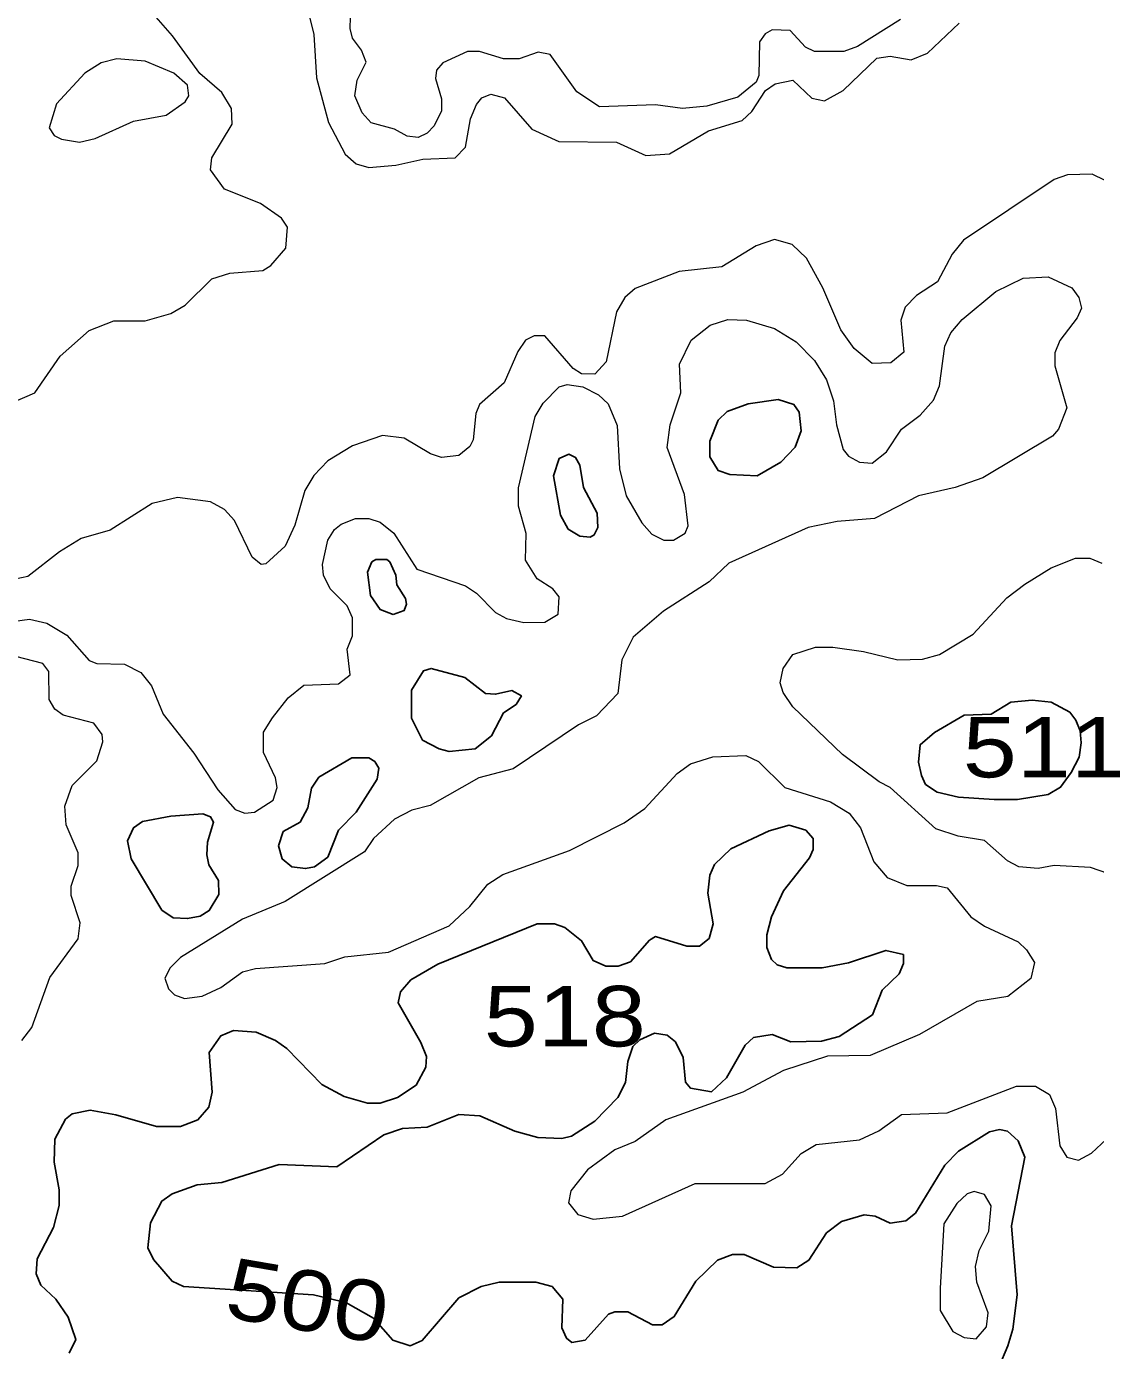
# Model space of a CAD drawing. Extents: x 577 to 602.9, y 7483.8 to 7511.6.
# Drawn here: x 591.332 to 592.745, y 7498.971 to 7500.722 of the extents above; entities that cross this region are included whole.
import ezdxf
from ezdxf.enums import TextEntityAlignment as Align

# ---------------------------------------------------------------- set-up
doc = ezdxf.new("R2010")
doc.units = 0
doc.header["$LTSCALE"] = 0.032
doc.layers.add('1', color=7, linetype='Continuous', lineweight=25)
doc.layers.add('2', color=7, linetype='Continuous', lineweight=13)
doc.layers.add('61', color=7, linetype='Continuous')

msp = doc.modelspace()

# ---------------------------------------------------------------- linework, layer by layer
at = {"layer": '1'}
for points in [[(592.2618, 7500.1298), (592.2979, 7500.1278), (592.3289, 7500.1461), (592.3479, 7500.166), (592.3559, 7500.1874), (592.3535, 7500.2121), (592.3464, 7500.2224), (592.3257, 7500.2288), (592.2859, 7500.2232), (592.2581, 7500.2129), (592.2462, 7500.2017), (592.235, 7500.1739), (592.235, 7500.1532), (592.2462, 7500.135)], [(592.0479, 7500.0574), (592.0633, 7500.0483), (592.0768, 7500.0467), (592.0824, 7500.0499), (592.0871, 7500.0594), (592.0863, 7500.0785), (592.068, 7500.1127), (592.0633, 7500.1421), (592.0577, 7500.1524), (592.049, 7500.1564), (592.0362, 7500.1509), (592.0283, 7500.1278), (592.0378, 7500.0761)], [(591.8167, 7499.9447), (591.8311, 7499.9497), (591.8343, 7499.9584), (591.8327, 7499.9656), (591.8215, 7499.9839), (591.82, 7499.9966), (591.812, 7500.0141), (591.808, 7500.0173), (591.7937, 7500.0173), (591.7881, 7500.0141), (591.7826, 7500.0006), (591.7866, 7499.9696), (591.7993, 7499.9513)], [(591.8553, 7499.7784), (591.8772, 7499.7668), (591.8907, 7499.7636), (591.9249, 7499.7668), (591.9464, 7499.7843), (591.9623, 7499.8145), (591.979, 7499.8256), (591.9861, 7499.8368), (591.9734, 7499.8439), (591.952, 7499.8391), (591.9384, 7499.8399), (591.9114, 7499.8614), (591.8669, 7499.8733), (591.8565, 7499.8702), (591.8406, 7499.8447), (591.8406, 7499.8073)], [(592.6824, 7499.7065), (592.699, 7499.7161), (592.7129, 7499.7358), (592.7234, 7499.7559), (592.726, 7499.7747), (592.7247, 7499.7908), (592.7193, 7499.805), (592.7113, 7499.8153), (592.6867, 7499.8288), (592.6612, 7499.8312), (592.6334, 7499.8288), (592.6072, 7499.8129), (592.5714, 7499.8113), (592.5324, 7499.7883), (592.5133, 7499.7724), (592.511, 7499.7493), (592.5149, 7499.7318), (592.5205, 7499.7199), (592.5356, 7499.7095), (592.5642, 7499.7032), (592.6112, 7499.7), (592.6422, 7499.7)], [(591.6711, 7499.6574), (591.6935, 7499.6698), (591.7039, 7499.6889), (591.7086, 7499.7151), (591.7182, 7499.7294), (591.7619, 7499.7549), (591.7842, 7499.7549), (591.7921, 7499.7501), (591.7977, 7499.7413), (591.7953, 7499.727), (591.7675, 7499.6833), (591.7444, 7499.6594), (591.7301, 7499.6237), (591.7126, 7499.6109), (591.7007, 7499.6085), (591.6824, 7499.6109), (591.6697, 7499.6213), (591.6649, 7499.6388)], [(591.5702, 7499.6268), (591.5711, 7499.6435), (591.579, 7499.6698), (591.575, 7499.6769), (591.5647, 7499.6809), (591.5226, 7499.6777), (591.4852, 7499.6706), (591.4733, 7499.6626), (591.4653, 7499.6451), (591.4701, 7499.6213), (591.5106, 7499.5537), (591.5257, 7499.5433), (591.5448, 7499.5425), (591.5615, 7499.5457), (591.5734, 7499.5529), (591.5862, 7499.5744), (591.5854, 7499.5926), (591.5727, 7499.6133)]]:
    msp.add_lwpolyline(points, close=True, dxfattribs=at)
for points in [[(591.3882, 7498.9676), (591.3969, 7498.9859), (591.3866, 7499.0153), (591.3707, 7499.0392), (591.3508, 7499.0575), (591.3444, 7499.0726), (591.346, 7499.0925), (591.3675, 7499.1338), (591.3747, 7499.1632), (591.3747, 7499.1839), (591.3683, 7499.2205), (591.3691, 7499.2507), (591.3834, 7499.277), (591.3921, 7499.2841), (591.416, 7499.2889), (591.4499, 7499.2827), (591.5035, 7499.2674), (591.5353, 7499.2674), (591.5583, 7499.2762), (591.5727, 7499.2929), (591.5774, 7499.3127), (591.5734, 7499.3652), (591.5886, 7499.3875), (591.6053, 7499.3946), (591.6355, 7499.3923), (591.6609, 7499.3811), (591.676, 7499.3708), (591.7221, 7499.3231), (591.7516, 7499.3072), (591.7826, 7499.2984), (591.7993, 7499.2984), (591.8223, 7499.3056), (591.847, 7499.3223), (591.8598, 7499.346), (591.8607, 7499.36), (591.8532, 7499.3787), (591.8231, 7499.4312), (591.8263, 7499.4455), (591.8398, 7499.4614), (591.8756, 7499.4821), (592.0068, 7499.5354), (592.0299, 7499.5354), (592.0434, 7499.5306), (592.0657, 7499.5131), (592.0808, 7499.4869), (592.0975, 7499.4797), (592.1142, 7499.4797), (592.1301, 7499.4853), (592.1555, 7499.5139), (592.1635, 7499.5187), (592.2048, 7499.506), (592.2215, 7499.506), (592.2342, 7499.5163), (592.2398, 7499.5354), (592.2326, 7499.5759), (592.235, 7499.5998), (592.2414, 7499.6141), (592.2629, 7499.6348), (592.3138, 7499.6586), (592.34, 7499.6658), (592.3623, 7499.6594)], [(592.3623, 7499.6594), (592.3718, 7499.6483), (592.3718, 7499.634), (592.367, 7499.6229), (592.3328, 7499.5791), (592.3169, 7499.5449), (592.3106, 7499.5211), (592.3106, 7499.5044), (592.3169, 7499.4885), (592.3241, 7499.4813), (592.3368, 7499.4773), (592.3837, 7499.4773), (592.4187, 7499.4837), (592.468, 7499.5004), (592.4911, 7499.4948), (592.4911, 7499.4829), (592.4855, 7499.4694), (592.4632, 7499.4479), (592.4505, 7499.4153), (592.406, 7499.3867), (592.3829, 7499.3803), (592.3424, 7499.3795), (592.3177, 7499.3891), (592.2931, 7499.3851), (592.2819, 7499.3748), (592.2573, 7499.3318), (592.2374, 7499.3135), (592.2096, 7499.3183), (592.2032, 7499.3263), (592.2, 7499.3589), (592.1897, 7499.3795), (592.1786, 7499.3883), (592.1619, 7499.3907), (592.1428, 7499.3819), (592.1333, 7499.3732), (592.1269, 7499.3533), (592.1237, 7499.3255), (592.1134, 7499.3056), (592.0832, 7499.2746), (592.0521, 7499.2547), (592.0394, 7499.2515), (592.0076, 7499.2531), (591.9774, 7499.2611), (591.9313, 7499.2817), (591.9034, 7499.2833), (591.8613, 7499.2666), (591.8287, 7499.265), (591.804, 7499.2563), (591.742, 7499.2141), (591.6657, 7499.2173), (591.5901, 7499.1935), (591.5575, 7499.1903), (591.5241, 7499.1784), (591.5106, 7499.1688), (591.4955, 7499.1402), (591.4923, 7499.1068), (591.4995, 7499.0917), (591.5241, 7499.0631), (591.5393, 7499.0559), (591.7112, 7499.0448), (591.7541, 7499.0345), (591.7905, 7499.0138), (591.816, 7498.9851), (591.839, 7498.9772), (591.8549, 7498.9843), (591.9034, 7499.0408), (591.9329, 7499.0559), (591.9567, 7499.0615), (592.0052, 7499.0615), (592.0267, 7499.0559), (592.041, 7499.0392), (592.0394, 7499.001), (592.0458, 7498.9875), (592.0529, 7498.9819), (592.0704, 7498.9851), (592.1014, 7499.0193), (592.1094, 7499.0225), (592.1269, 7499.0225), (592.1595, 7499.005), (592.1722, 7499.005), (592.1881, 7499.0161), (592.2167, 7499.0631), (592.2454, 7499.0909), (592.2652, 7499.098), (592.2804, 7499.098), (592.3193, 7499.0813), (592.3503, 7499.0805), (592.3662, 7499.0909), (592.3893, 7499.1267), (592.4092, 7499.1418), (592.4394, 7499.1505), (592.4537, 7499.1489), (592.4736, 7499.1394), (592.4943, 7499.1426), (592.507, 7499.1529), (592.5459, 7499.2165), (592.5642, 7499.2348), (592.6048, 7499.2603), (592.6183, 7499.2634), (592.6286, 7499.2611), (592.643, 7499.2483)], [(592.643, 7499.2483), (592.6517, 7499.2269), (592.6342, 7499.1362), (592.6414, 7499.0448), (592.6358, 7498.9994), (592.6294, 7498.9772), (592.6175, 7498.9493)]]:
    msp.add_lwpolyline(points, dxfattribs=at)
at = {"layer": '2'}
for points in [[(591.6029, 7500.6136), (591.5901, 7500.6351), (591.5607, 7500.6598), (591.5249, 7500.7099), (591.4971, 7500.7417)], [(591.7054, 7500.7369), (591.7118, 7500.7115), (591.715, 7500.6542), (591.7309, 7500.5954), (591.7532, 7500.5532), (591.7675, 7500.5405), (591.7842, 7500.5357), (591.82, 7500.5389), (591.8557, 7500.5469), (591.8987, 7500.5484), (591.9122, 7500.5628), (591.9186, 7500.6001), (591.9265, 7500.6192), (591.9337, 7500.628), (591.9456, 7500.6327), (591.9639, 7500.628), (591.9997, 7500.5866), (592.0354, 7500.5699), (592.1118, 7500.5691), (592.1507, 7500.5516), (592.1818, 7500.554), (592.2334, 7500.5842), (592.278, 7500.5977), (592.2907, 7500.6097), (592.309, 7500.6375), (592.3217, 7500.6463), (592.3448, 7500.651), (592.3702, 7500.6272), (592.3869, 7500.624), (592.4116, 7500.6375), (592.4561, 7500.6804), (592.4736, 7500.6828), (592.5014, 7500.6781), (592.5229, 7500.6868), (592.565, 7500.7266)], [(592.4871, 7500.7313), (592.4306, 7500.6956), (592.4124, 7500.6892), (592.3734, 7500.6892), (592.3615, 7500.6948), (592.3416, 7500.717), (592.3177, 7500.7178), (592.3082, 7500.7123), (592.301, 7500.7019), (592.3002, 7500.6574), (592.2963, 7500.6486), (592.2724, 7500.6288), (592.2311, 7500.6168), (592.1992, 7500.6136), (592.1635, 7500.6184), (592.0895, 7500.616), (592.0593, 7500.6359), (592.0243, 7500.6852), (592.0084, 7500.6884), (591.983, 7500.6796), (591.9623, 7500.6796), (591.9305, 7500.6892), (591.9146, 7500.6892), (591.882, 7500.6741), (591.874, 7500.6645), (591.8724, 7500.6534), (591.8804, 7500.6264), (591.8804, 7500.6105), (591.8708, 7500.5906), (591.8613, 7500.581), (591.8494, 7500.5755), (591.8351, 7500.5771), (591.8184, 7500.5866), (591.7873, 7500.5946), (591.7754, 7500.6081), (591.7659, 7500.6303), (591.7691, 7500.651), (591.781, 7500.6749), (591.7746, 7500.6908), (591.7627, 7500.7067), (591.7595, 7500.7194), (591.7603, 7500.7345)], [(591.3134, 7500.2248), (591.3428, 7500.2375), (591.3762, 7500.286), (591.4144, 7500.3202), (591.447, 7500.333), (591.4884, 7500.333), (591.5226, 7500.3425), (591.5416, 7500.3536), (591.5766, 7500.3886), (591.6005, 7500.3958), (591.6442, 7500.3997), (591.6546, 7500.4061), (591.6744, 7500.4292), (591.6768, 7500.457), (591.6689, 7500.4689), (591.641, 7500.488), (591.5933, 7500.5071), (591.575, 7500.5325), (591.5766, 7500.5484), (591.6037, 7500.593), (591.6029, 7500.6136)], [(592.775, 7500.5103), (592.7408, 7500.527), (592.7082, 7500.5262), (592.6907, 7500.5198), (592.5706, 7500.4395), (592.5555, 7500.4212), (592.5364, 7500.3846), (592.5086, 7500.3663), (592.4935, 7500.3512), (592.4879, 7500.3337), (592.4919, 7500.2916), (592.4744, 7500.2773), (592.4497, 7500.2765), (592.4259, 7500.2964), (592.4084, 7500.321), (592.3845, 7500.3767), (592.3631, 7500.4157), (592.344, 7500.4339), (592.3209, 7500.4403), (592.2963, 7500.4323), (592.2509, 7500.4045), (592.1945, 7500.3982), (592.1364, 7500.3759), (592.1229, 7500.364), (592.1118, 7500.3449), (592.0983, 7500.2789), (592.0832, 7500.2622), (592.0657, 7500.263), (592.0545, 7500.2701), (592.0172, 7500.3131), (592.0028, 7500.3131), (591.9917, 7500.3075), (591.9814, 7500.2924), (591.9631, 7500.251), (591.9305, 7500.2224), (591.9257, 7500.2105), (591.9225, 7500.1755), (591.9178, 7500.1668), (591.9034, 7500.1548), (591.8804, 7500.1524), (591.8661, 7500.1572), (591.8311, 7500.1779), (591.8025, 7500.1811), (591.7627, 7500.1676), (591.7301, 7500.1477), (591.7118, 7500.1286), (591.6999, 7500.1087), (591.6864, 7500.0626), (591.6736, 7500.0348), (591.6482, 7500.0117), (591.6418, 7500.0109), (591.6299, 7500.0204), (591.6068, 7500.069), (591.5933, 7500.0833), (591.575, 7500.0936), (591.5313, 7500.0992), (591.4979, 7500.0912), (591.4422, 7500.0562), (591.4041, 7500.0451), (591.3754, 7500.0276), (591.3333, 7499.995), (591.2745, 7499.9823)], [(591.5846, 7499.7127), (591.6076, 7499.6865), (591.6204, 7499.6817), (591.6331, 7499.6833), (591.6577, 7499.6992), (591.6633, 7499.7159), (591.6609, 7499.7286), (591.645, 7499.762), (591.645, 7499.7891), (591.6569, 7499.8081), (591.6776, 7499.8344), (591.6983, 7499.8511), (591.7444, 7499.8527), (591.7595, 7499.8646), (591.7555, 7499.8988), (591.7627, 7499.9163), (591.7627, 7499.9401), (591.7555, 7499.956), (591.7333, 7499.9783), (591.7245, 7499.9966), (591.7229, 7500.0109), (591.7301, 7500.0427), (591.7388, 7500.057), (591.7476, 7500.0642), (591.7667, 7500.0713), (591.7842, 7500.0713), (591.7993, 7500.0666), (591.8176, 7500.0523), (591.8478, 7500.0045), (591.9122, 7499.9823), (591.9265, 7499.9727), (591.952, 7499.9473), (591.9663, 7499.9393), (591.9893, 7499.9338), (592.0172, 7499.9346), (592.0346, 7499.9449), (592.0362, 7499.968), (592.0275, 7499.9783), (592.0068, 7499.9918), (591.9917, 7500.0165), (591.9925, 7500.0515), (591.9822, 7500.088), (591.9822, 7500.1119), (592.0044, 7500.2065), (592.0148, 7500.224), (592.0362, 7500.2455), (592.0466, 7500.2487), (592.0673, 7500.2455), (592.0879, 7500.2351), (592.1006, 7500.2232), (592.1126, 7500.1946), (592.1158, 7500.1373), (592.1245, 7500.1016), (592.1452, 7500.0658), (592.1587, 7500.0507), (592.1746, 7500.0427), (592.1873, 7500.0427), (592.2024, 7500.0523), (592.2064, 7500.0618), (592.2016, 7500.1031), (592.1786, 7500.1652), (592.1826, 7500.1954), (592.1969, 7500.2375), (592.1953, 7500.2757), (592.2104, 7500.3075), (592.2358, 7500.3274), (592.2589, 7500.3345), (592.2835, 7500.3337), (592.3209, 7500.3226), (592.3495, 7500.3051), (592.3734, 7500.2805), (592.3893, 7500.255), (592.3988, 7500.2272), (592.4028, 7500.1954), (592.4116, 7500.1628), (592.4187, 7500.154), (592.433, 7500.1461), (592.4497, 7500.1445), (592.4688, 7500.1596), (592.4887, 7500.1898), (592.5133, 7500.2081), (592.5308, 7500.228), (592.5388, 7500.2471), (592.5459, 7500.2996), (592.5539, 7500.317), (592.569, 7500.3345), (592.6135, 7500.3719), (592.6493, 7500.3894), (592.6827, 7500.391), (592.7137, 7500.3767), (592.7233, 7500.364), (592.7265, 7500.3497), (592.7209, 7500.3369), (592.6978, 7500.3067), (592.6915, 7500.2908), (592.6915, 7500.2733), (592.7074, 7500.2177), (592.6962, 7500.1898), (592.6883, 7500.1803), (592.596, 7500.1254), (592.5595, 7500.1127)], [(592.5595, 7500.1127), (592.511, 7500.1016), (592.4529, 7500.0713), (592.4036, 7500.0674), (592.3654, 7500.0594), (592.2605, 7500.0125), (592.2342, 7499.9878), (592.1738, 7499.9489), (592.134, 7499.9147), (592.1189, 7499.8845), (592.1134, 7499.8399), (592.0855, 7499.8105), (592.0617, 7499.7986), (591.975, 7499.7405), (591.9297, 7499.7286), (591.8653, 7499.692), (591.8414, 7499.6857), (591.8184, 7499.6738), (591.7905, 7499.6483), (591.7786, 7499.6308), (591.6737, 7499.565), (591.6172, 7499.5418), (591.5353, 7499.4909), (591.5218, 7499.4773), (591.5146, 7499.4638), (591.5194, 7499.4495), (591.5273, 7499.4416), (591.5408, 7499.4368), (591.5639, 7499.44), (591.5886, 7499.4511), (591.6172, 7499.4718), (591.6347, 7499.4765), (591.7261, 7499.4829), (591.7524, 7499.4917), (591.8104, 7499.498), (591.8907, 7499.533), (591.9178, 7499.5585), (591.9416, 7499.5879), (591.9615, 7499.6006), (592.0498, 7499.6324), (592.1221, 7499.669), (592.1492, 7499.6881), (592.1921, 7499.7342), (592.2096, 7499.7469), (592.239, 7499.7564), (592.2827, 7499.758), (592.2994, 7499.7501), (592.3344, 7499.7159), (592.3949, 7499.6968), (592.4195, 7499.6817), (592.4346, 7499.6626), (592.4521, 7499.6173), (592.4696, 7499.5966), (592.4959, 7499.5863), (592.5348, 7499.5863), (592.5491, 7499.5831), (592.5801, 7499.5449), (592.5984, 7499.5322), (592.643, 7499.5115), (592.6541, 7499.5012), (592.6644, 7499.4845), (592.6597, 7499.463), (592.6294, 7499.4392), (592.5881, 7499.4328), (592.5125, 7499.3891), (592.4473, 7499.3612), (592.3909, 7499.3605), (592.3328, 7499.3414), (592.2788, 7499.3127), (592.177, 7499.2762), (592.1364, 7499.2475), (592.1094, 7499.2364), (592.0736, 7499.2102), (592.0513, 7499.1823), (592.0482, 7499.1664), (592.0609, 7499.1513), (592.0808, 7499.145), (592.1197, 7499.1489), (592.2159, 7499.1919), (592.3082, 7499.1919), (592.3312, 7499.2046), (592.3559, 7499.2316), (592.3758, 7499.2436), (592.433, 7499.2499), (592.4585, 7499.2618), (592.4887, 7499.2833), (592.5491, 7499.2857), (592.6406, 7499.3207), (592.666, 7499.3207), (592.6843, 7499.3096), (592.6923, 7499.2913), (592.6978, 7499.242), (592.7074, 7499.2269), (592.7225, 7499.2229), (592.74, 7499.2324), (592.7598, 7499.2507)], [(592.4839, 7499.8845), (592.5165, 7499.8853), (592.5388, 7499.8916), (592.5833, 7499.9187), (592.6278, 7499.9664), (592.6517, 7499.9847), (592.6867, 7500.0061), (592.7185, 7500.0189), (592.7376, 7500.0189), (592.7535, 7500.0125)], [(591.3134, 7499.9354), (591.3357, 7499.9385), (591.3587, 7499.933), (591.385, 7499.9171), (591.4144, 7499.8837), (591.4247, 7499.8797), (591.4613, 7499.8789), (591.4828, 7499.8678), (591.4971, 7499.8503), (591.5122, 7499.8129), (591.5528, 7499.7612), (591.5846, 7499.7127)], [(592.7384, 7499.6101), (592.6907, 7499.6125), (592.6692, 7499.6085), (592.6438, 7499.6109), (592.6286, 7499.6189), (592.5984, 7499.6459), (592.5634, 7499.6515), (592.534, 7499.661), (592.4736, 7499.7159), (592.4593, 7499.7231), (592.4108, 7499.7596), (592.3448, 7499.8224), (592.332, 7499.8415), (592.3281, 7499.8543), (592.332, 7499.8733), (592.3448, 7499.8916), (592.375, 7499.9012), (592.398, 7499.9012), (592.4385, 7499.8955), (592.4839, 7499.8845)], [(591.3254, 7499.3811), (591.3389, 7499.3986), (591.3627, 7499.4646), (591.4001, 7499.5155), (591.4025, 7499.537), (591.3906, 7499.5728), (591.3906, 7499.5855), (591.4001, 7499.6125), (591.4001, 7499.6292), (591.3842, 7499.6666), (591.3826, 7499.6912), (591.3921, 7499.7183), (591.4247, 7499.7509), (591.4327, 7499.7763), (591.4319, 7499.7859), (591.4208, 7499.801), (591.3802, 7499.8113), (591.3691, 7499.8193), (591.3619, 7499.832), (591.3611, 7499.8694), (591.3532, 7499.8797), (591.3174, 7499.8892)], [(592.7614, 7499.6022), (592.7384, 7499.6101)]]:
    msp.add_lwpolyline(points, dxfattribs=at)
for points in [[(591.3778, 7500.5731), (591.4017, 7500.5691), (591.4224, 7500.5739), (591.4733, 7500.597), (591.5162, 7500.6049), (591.5416, 7500.6224), (591.5464, 7500.6303), (591.5448, 7500.6447), (591.5265, 7500.6606), (591.4884, 7500.6765), (591.451, 7500.6796), (591.4303, 7500.6741), (591.4088, 7500.6606), (591.3715, 7500.62), (591.3619, 7500.5882), (591.3683, 7500.5779)], [(592.5396, 7499.0535), (592.5396, 7499.0241), (592.5563, 7498.9963), (592.5714, 7498.9883), (592.5873, 7498.9867), (592.6008, 7499.0026), (592.6032, 7499.0209), (592.5881, 7499.0615), (592.5865, 7499.0821), (592.5913, 7499.1036), (592.604, 7499.1291), (592.6072, 7499.1625), (592.5984, 7499.1776), (592.5849, 7499.1815), (592.5754, 7499.1784), (592.5619, 7499.1656), (592.5444, 7499.1386)]]:
    msp.add_lwpolyline(points, close=True, dxfattribs=at)

# ---------------------------------------------------------------- texts
at = {"layer": '61', "width": 1.2}
for s, p in [('511', (592.6768, 7499.7292)), ('518', (592.0435, 7499.3734))]:
    msp.add_text(s, height=0.08, dxfattribs=at).set_placement(p, align=Align.CENTER)
msp.add_text('500', height=0.08, rotation=350.267, dxfattribs=at).set_placement((591.6967, 7498.9978), align=Align.CENTER)

doc.saveas('drawing.dxf')
